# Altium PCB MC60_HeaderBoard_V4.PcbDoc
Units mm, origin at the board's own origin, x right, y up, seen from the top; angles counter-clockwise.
Board outline 51 x 30.45 mm, 2 copper layers (Top Layer, Bottom Layer); 33 components, 37 nets, 147 pads, 70 vias.
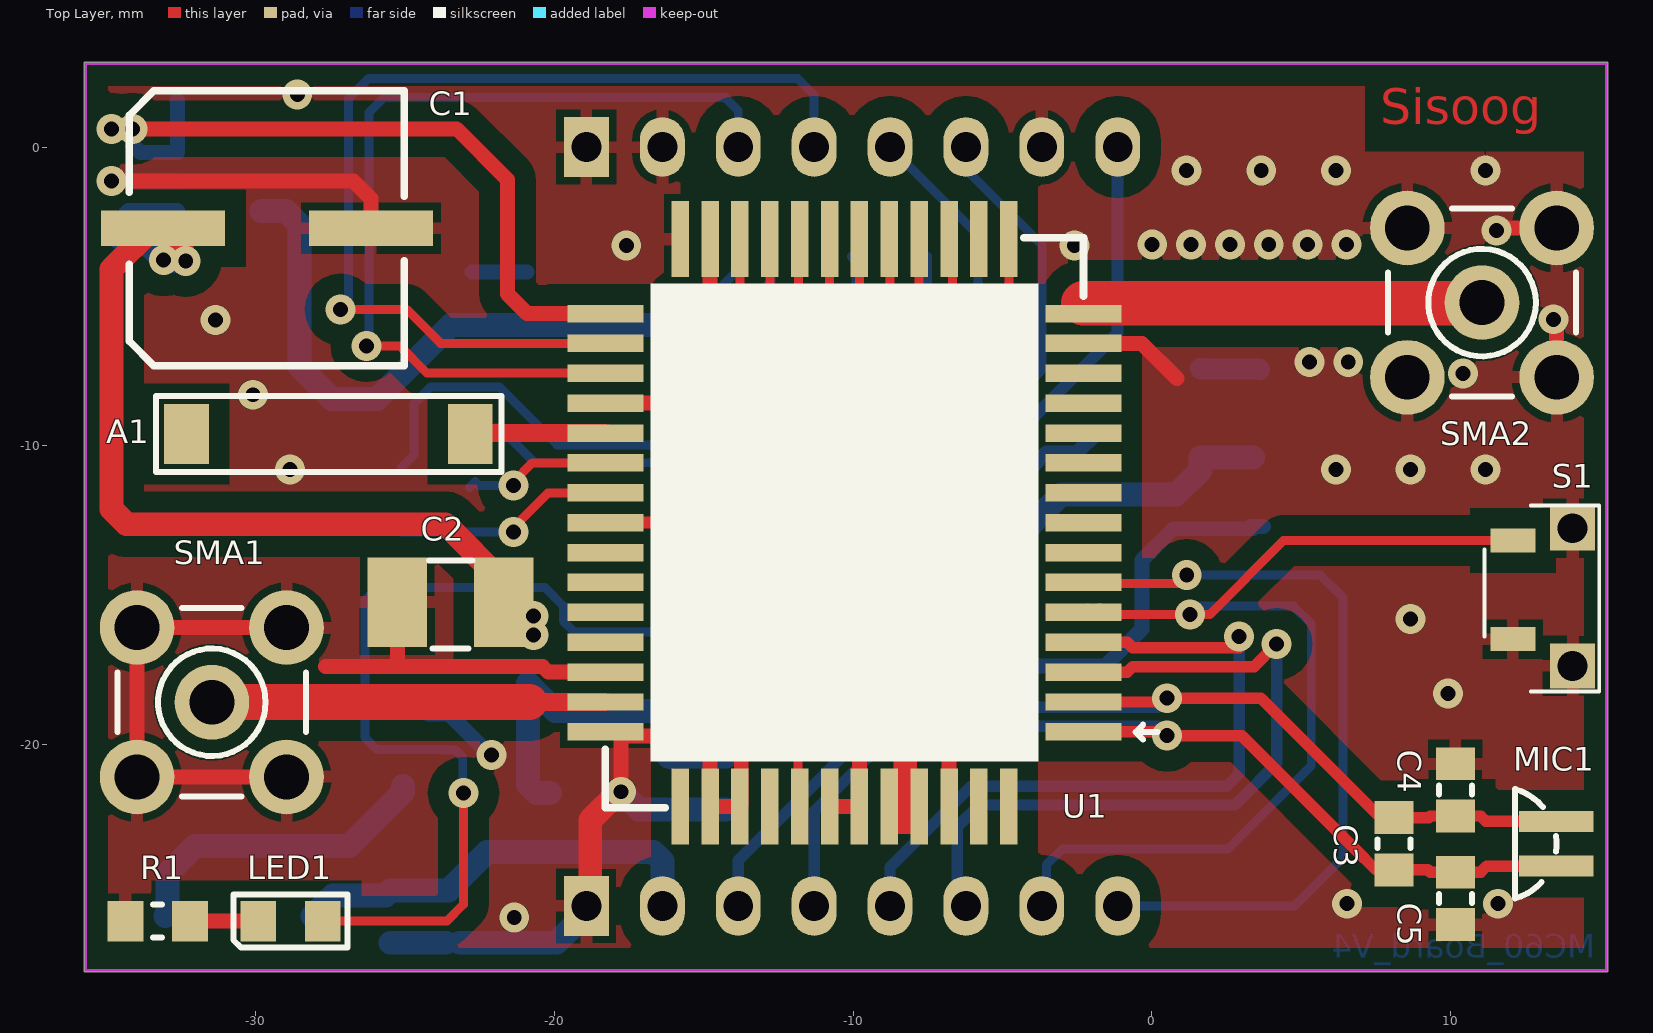
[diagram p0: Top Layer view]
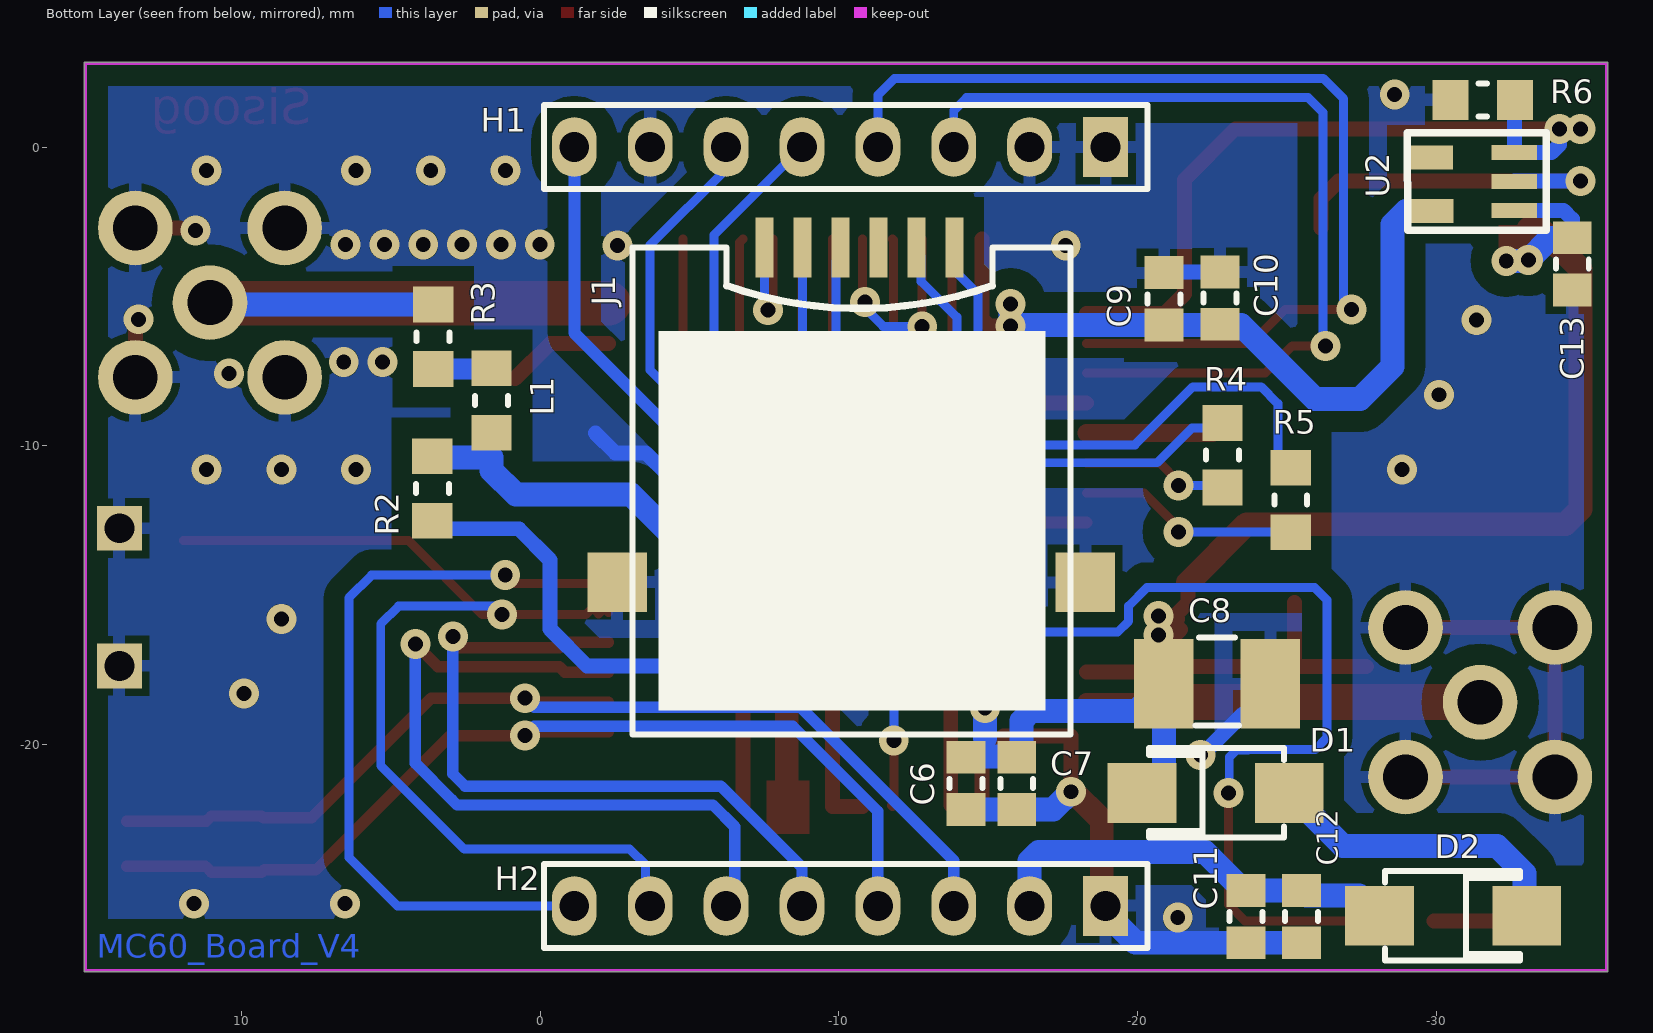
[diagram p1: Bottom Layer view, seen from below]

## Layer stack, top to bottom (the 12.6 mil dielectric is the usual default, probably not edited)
Top Solder: solder mask 0.0102, Solder Resist, Dk 3.5
Top Layer: signal copper 0.0356
Dielectric 1: dielectric 0.32, FR-4, Dk 4.8
Bottom Layer: signal copper 0.0356
Bottom Solder: solder mask 0.0102, Solder Resist, Dk 3.5

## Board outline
-35.687,-27.609 cw(c-35.687,-27.559) -35.737,-27.559 -35.737,2.794 cw(c-35.687,2.794) -35.687,2.844 15.214,2.844 cw(c15.214,2.794) 15.264,2.794 15.264,-27.559 cw(c15.214,-27.559) 15.214,-27.609

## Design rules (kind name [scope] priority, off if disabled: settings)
Clearance [All] p1: gap=0.3 except(0.7: Arc-Poly Track-Poly SMDPad-Poly THPad-Poly Via-Poly Fill-Poly Poly-Poly)
DiffPairsRouting [All] p1: maxlimit=0.254 minlimit=0.254 mostfreqgap=0.254 toplayer_minwidth=0.381 toplayer_maxwidth=0.381 toplayer_prefwidth=0.381 bottomlayer_minwidth=0.381 bottomlayer_maxwidth=0.381 bottomlayer_prefwidth=0.381 maxuncoupledlength=12.7
PolygonConnect [ISPAd] p1: connectstyle=Relief reliefconductorwidth=0.4 reliefentries=4 polygonreliefangle="90 Angle" airgapwidth=0.254
RoutingVias [All] p1: holewidth=0.5 width=1 viastyle="Through Hole" minholewidth=0.5 minwidth=0.5 maxholewidth=0.711 maxwidth=1.27
SolderMaskExpansion [All] p1: expansion=0.102
Width [All] p1: maxlimit=10 minlimit=0.254 preferedwidth=0.3
29 further rules are at their usual default settings.

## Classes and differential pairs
component class Main: A1 C13 H1 H2 J1 L1 R2 R3 R4 R5 SMA1 SMA2 U1
component class IO: C1 C2 C3 C4 C5 C6 C7 C8 C9 C10 C11 C12 D1 D2 LED1 MIC1 R1 R6 S1 U1
differential pair SPK: +SPK_P -SPK_N
differential pair MIC: +MIC_P -MIC_N

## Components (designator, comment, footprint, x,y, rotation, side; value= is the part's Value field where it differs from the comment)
A1 "AT9520 ANTENA 2.4GHz" "AT9520 ANTENA 2.4GHz" -27.559,-9.601 r0 top
C1 "1000uF 6V" "ALUMINUM \"CAP\"" -29.616,-2.718 r270 top (schematic designator C4)
C2 "220uF" "Tantalum Case B" -23.47,-15.24 r180 top (schematic designator C11)
C3 "10nF" "SMD 0805" 8.103,-23.317 r270 top (schematic designator C2)
C4 "10nF" "SMD 0805" 10.16,-21.514 r270 top (schematic designator C3)
C5 "10nF" "SMD 0805" 10.16,-25.146 r270 top (schematic designator C1)
C6 "100nF" "SMD 0805" -14.249,-21.297 r90 bottom (schematic designator C8)
C7 "10uF" "SMD 0805" -15.951,-21.297 r90 bottom
C8 "220uF Tantal" "Tantalum Case B" -22.657,-17.958 r180 bottom (schematic designator C13)
C9 "100nF" "SMD 0805" -20.879,-5.08 r270 bottom (schematic designator C10)
C10 "10uF" "SMD 0805" -22.758,-5.055 r270 bottom (schematic designator C9)
C11 "100nF" "SMD 0805" -23.622,-25.756 r90 bottom (schematic designator C5)
C12 "10uF" "SMD 0805" -25.476,-25.756 r90 bottom (schematic designator C6)
C13 "10uF" "SMD 0805" -34.544,-3.912 r90 bottom (schematic designator C12)
D1 "SS34" "DIODE DO-214AC SMD" -22.606,-21.615 r270 bottom (schematic designator D2)
D2 "M7" "DIODE DO-214AC SMD" -30.556,-25.73 r90 bottom (schematic designator D1)
H1 "HEDER 8PIN" "HEADER 8X1" -10.033,0 r0 bottom locked (schematic designator H2)
H2 "HEDER 8PIN" "HEADER 8X1" -10.033,-25.4 r0 bottom locked (schematic designator H1)
J1 "SIM CARD 6PIN SMT" "SIM CART 6PIN SMT TYPE" -10.414,-8.966 r0 bottom
L1 "feride bide 120R" 0805_1/8W 1.626,-8.484 r270 bottom
LED1 "LED SMD" "LED 0805" -28.829,-25.908 r180 top
MIC1 "Microphone" "Microphone SMD" 13.538,-23.317 r180 top
R1 "1K" 0805_1/8W -33.274,-25.908 r0 top (schematic designator R5)
R2 "10K" 0805_1/8W 3.607,-11.43 r90 bottom (schematic designator R6)
R3 "10R" 0805_1/8W 3.581,-6.35 r90 bottom (schematic designator R4)
R4 "10R" 0805_1/8W -22.835,-10.312 r90 bottom (schematic designator R3)
R5 "10R" 0805_1/8W -25.121,-11.811 r90 bottom (schematic designator R2)
R6 "100K" 0805_1/8W -31.547,1.575 r180 bottom (schematic designator R1)
S1 "Switch PB" "Switch - Push to On SMD stand 4.62mm" 13.081,-15.062 r180 top
SMA1 "SMA Antena" SMA -31.46,-18.582 r180 top locked
SMA2 "SMA GNSS" SMA 11.049,-5.207 r0 top
U1 "MC60" MC60 -10.287,-12.573 r180 top (schematic designator U2)
U2 "L2980" TSOT23 -32.604,-0.186 r270 bottom (schematic designator U1)

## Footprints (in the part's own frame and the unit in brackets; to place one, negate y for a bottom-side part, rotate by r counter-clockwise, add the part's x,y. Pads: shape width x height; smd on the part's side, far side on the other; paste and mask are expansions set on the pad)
0805_1/8W [mm] "Chip Resistor, 2-Leads, Body 2.0x1.3mm, IPC High Density _ (0.100 W)"
  rect 1.2x1.35 smd: 1(-1.079,0) 2(1.079,0)
  silkscreen extent -0.15,-0.55 0.15,0.55, body extent -1.02,-0.63 1.02,0.64, height 0.6
"ALUMINUM \"CAP\"" [mm]
  rect 1.2x4.16 smd: 1(0,-3.48) 2(0,3.48)
  silkscreen extent -4.6,-4.6 4.6,4.6
"AT9520 ANTENA 2.4GHz" [mm]
  rect 1.5x2 smd: 1(-4.75,0) 2(4.75,0)
  silkscreen extent -5.77,-1.27 5.79,1.27, body extent -4.88,-1.05 4.62,1.05, height 1.05
"DIODE DO-214AC SMD" [mm]
  rect 2x2.3 smd: 1(0,2.462) 2(0,-2.462)
  silkscreen extent -1.5,-2.34 1.5,2.29, body extent -1.32,-2.69 1.47,2.79, height 2.24
"HEADER 8X1" [mm]
  rect 1.5x2 hole 1: 1(-8.89,0)
  oval 1.5x2 hole 1: 2(-6.35,0) 3(-3.81,0) 4(-1.27,0) 5(1.27,0) 6(3.81,0) 7(6.35,0) 8(8.89,0)
  silkscreen extent -10.29,-1.4 9.91,1.4, body extent -10.08,-1.22 10.24,1.32, height 8.38
"LED 0805" [mm]
  rect 1.2x1.35 smd: 1(-1.079,0) 2(1.079,0)
  silkscreen extent -1.91,-0.89 1.91,0.89, body extent -1.65,-0.69 1.65,0.76, height 1.36
MC60 [mm]
  rect 2.54x0.584 smd: 1(-8,7) 2(-8,6) 3(-8,5) 4(-8,4) 5(-8,3) 6(-8,2) 7(-8,1) 8(-8,0) 9(-8,-1) 10(-8,-2) 11(-8,-3) 12(-8,-4) 13(-8,-5) 14(-8,-6) 15(-8,-7) 28(8,-7) 29(8,-6) 30(8,-5) 31(8,-4) 32(8,-3) 33(8,-2) 34(8,-1) 35(8,0) 36(8,1) 37(8,2) 38(8,3) 39(8,4) 40(8,5) 41(8,6) 42(8,7)
  rect 0.584x2.54 smd: 16(-5.5,-9.5) 17(-4.5,-9.492) 18(-3.5,-9.492) 19(-2.5,-9.492) 20(-1.5,-9.492) 21(-0.5,-9.492) 22(0.5,-9.492) 23(1.5,-9.492) 24(2.5,-9.492) 25(3.5,-9.492) 26(4.5,-9.492) 27(5.5,-9.492) 43(5.5,9.5) 44(4.5,9.492) 45(3.5,9.492) 46(2.5,9.492) 47(1.5,9.492) 48(0.5,9.492) 49(-0.5,9.492) 50(-1.5,9.492) 51(-2.5,9.492) 52(-3.5,9.492) 53(-4.5,9.492) 54(-5.5,9.5)
  silkscreen extent -10.48,-9.54 8,9.54
"Microphone SMD" [mm]
  rect 2.5x0.7 smd: 1(0,0.75) 2(0,-0.75)
  silkscreen extent 0,-1.83 1.38,1.83
"SIM CART 6PIN SMT TYPE" [mm]
  rect 2x2 smd: 0(-7.83,5.6) 0(7.83,5.6)
  rect 0.6x2 smd: 1(-3.45,-5.6) 2(-2.18,-5.6) 3(-0.91,-5.6) 4(0.36,-5.6) 5(1.63,-5.6) 6(2.9,-5.6)
  silkscreen extent -7.33,-5.6 7.33,10.7, body extent -7.7,-5.86 7.7,10.44, height 2.07
SMA [mm]
  round 2.5 hole 1.5: 1(0,0) 2(-2.5,2.5) 2(-2.5,-2.5) 2(2.5,2.5) 2(2.5,-2.5)
  silkscreen extent -3.15,-3.15 3.15,3.15, body extent -3.27,-4.56 27.08,4.44, height 49.75
"SMD 0805" [mm]
  rect 1.1x1.3 smd: 1(-0.876,0) 2(0.876,0)
  silkscreen extent -0.15,-0.55 0.15,0.55, body extent -1.02,-0.63 1.02,0.63, height 0.65
"Switch - Push to On SMD stand 4.62mm" [mm]
  rect 1.5x1.5 hole 1: 0(-1,2.305) 0(-1,-2.305)
  rect 1.5x0.8 smd: 1(1,-1.895) 2(1,1.405)
  silkscreen extent -1.89,-3.07 1.95,3.16, body extent -4.31,-3.01 2.31,2.9, height 6.6
"Tantalum Case B" [mm]
  rect 2x3 smd: 1(-1.782,0) 2(1.782,0)
  silkscreen extent -0.73,-1.41 0.73,1.54
TSOT23 [mm]
  rect 0.5x1.524 smd: 1(1.94,0) 2(0.97,0) 3(0,0)
  rect 0.8x1.524 smd: 4(0.17,-2.81) 5(1.95,-2.8)
  silkscreen extent -0.67,-3.58 2.6,1.07, body extent -0.53,-2.64 2.47,-0.14, height 1.1

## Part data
C1 C2 C8: library part CAP
C3 C4 C5 C6 C7 C9 C10 C11 C12 C13: library part "CAP NON"
D1 D2: library part Diode
L1: library part Inductor, "Inductor"
LED1: library part "LED 2PIN"
R1 R2 R3 R4 R5 R6: library part RESISTOR
SMA2: library part "SMA Antena"

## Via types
v1: diameter 1, hole 0.5, Top Layer to Bottom Layer, 40 vias
v2: diameter 1, hole 0.5, Top Layer to Bottom Layer, tented both sides, 30 vias

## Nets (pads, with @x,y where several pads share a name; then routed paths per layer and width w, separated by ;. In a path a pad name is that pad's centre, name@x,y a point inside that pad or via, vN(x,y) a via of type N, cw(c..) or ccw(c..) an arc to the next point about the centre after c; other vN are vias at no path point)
3V3: C9.2 C10.2 U1.26 U2.5 | length 25
  Top Layer w0.5: v1(-15.748,-5.994) -15.037,-5.994 -14.787,-5.745 U1.26
  Bottom Layer w0.8: U2.5 -28.979,-2.136 -28.522,-2.593 -28.522,-7.343 -27.432,-8.433 -25.938,-8.433 -23.461,-5.956 C9.2 -15.787,-5.956 v1(-15.748,-5.994) v1(-15.748,-5.258)
4V3: C1.1 C2.1 C6.2 C7.2 C8.1 C13.2 D1.2 L1.2 R2.2 U1.50 U1.51 U2.1 | length 75.8
  Top Layer w0.5: C2.1@-21.687,-14.584 C2.1 C2.1@-21.234,-15.693 ; C2.1@-21.234,-16.358 -21.438,-16.154 C2.1@-21.105,-15.822 ; v1(-20.701,-16.332) -20.697,-16.332 -20.621,-16.408 -20.57,-16.358 -20.978,-15.949 C2.1@-21.105,-15.822 ; v1(-20.701,-15.697) -20.98,-15.697 C2.1@-21.082,-15.799 ; C2.1@-21.234,-15.693 C2.1@-21.129,-15.799 ; C2.1@-21.234,-15.693 -21.34,-15.799 C2.1@-21.129,-15.799 ; C2.1@-21.129,-15.799 C2.1@-21.082,-15.799 ; C2.1@-21.129,-15.799 C2.1@-21.105,-15.822 ; C2.1@-21.105,-15.822 C2.1@-21.082,-15.799
  Top Layer w0.8: C1.1 -33.452,-2.718 -34.823,-4.089 -34.823,-12.116 -34.315,-12.624 -23.647,-12.624 C2.1@-21.687,-14.584 ; v1@-14.859,-18.034 -14.859,-17.272 -14.224,-16.637 v1(-8.763,-16.637) -8.255,-17.145 v1(-8.255,-17.374) -8.255,-21.597 U1.51@-8.001,-21.851
  Bottom Layer w0.5: C13.2 -34.544,-2.413 -34.257,-2.126 U2.1
  Bottom Layer w0.8: C13.2 -33.82,-3.036 v1(-33.071,-3.785) -33.045,-3.81 v1(-32.334,-3.81) ; v1(-20.701,-16.332) -20.701,-16.387 -20.679,-16.408 v1@-20.677,-16.407 ; D1.2 -20.599,-21.615 -20.875,-21.34 C8.1 -19.96,-18.872 -16.434,-18.872 -16.104,-19.202 C7.2@-16.104,-20.396 ; C7.2@-16.18,-20.396 C7.2@-16.104,-20.396 ; C7.2@-16.104,-20.422 C7.2@-16.104,-20.396 ; -14.884,-19.774 v1(-14.884,-18.771) ; C6.2@-14.275,-20.371 -14.249,-20.396 C7.2@-16.104,-20.396 ; v1(-8.255,-17.374) -8.255,-17.043 -8.153,-16.942 -8.458,-16.637 -8.153,-16.637 -8.103,-16.688 -3.048,-11.633 0.813,-11.633 1.626,-10.82 1.626,-10.389 R2.2@3.39,-10.389
  other v1: -14.884,-18.034
5V: C11.2 C12.2 D2.1 H2.2 | length 14.2
  Bottom Layer w0.8: D2.1 -27.408,-25.044 -25.641,-25.044 C12.2 C11.2 -23.534,-24.88 -22.25,-23.597 -16.688,-23.597 -16.383,-23.901 H2.2
ADC: H2.8 U1.6 | length 26.1
  Top Layer w0.3: U1.6 -2.192,-14.478 -2.065,-14.605 0.889,-14.605 v1(1.168,-14.326)
  Bottom Layer w0.3: H2.8 4.775,-25.4 6.401,-23.774 6.401,-15.088 5.639,-14.326 v1(1.168,-14.326)
DBG_RXD: H1.3 U1.30 | length 30.2
  Top Layer w0.3: v1(-26.289,-6.655) -25.171,-6.655 -24.259,-7.567 U1.30@-18.287,-7.567
  Bottom Layer w0.3: v1(-26.289,-6.655) -26.203,-6.568 -26.203,1.153 -25.705,1.651 -14.275,1.651 -13.843,1.219 H1.3
DBG_TXD: H1.4 U1.29 | length 34.1
  Top Layer w0.3: v1(-27.153,-5.436) -24.943,-5.436 -23.805,-6.573 U1.29
  Bottom Layer w0.3: v1@-26.889,-5.324 -26.889,1.61 -26.205,2.294 -11.862,2.294 -11.303,1.735 H1.4
GND: C1.2 C2.2 C4.1 C5.2 C6.1 C7.1 C8.2 C9.1 C10.1 C11.1 C12.1 C13.1 H1.1 H1.2 H1.7 H2.1 J1.0 R1.1 R6.1 S1.0 S1.2 SMA1.2 SMA2.2 U1.14 U1.27 U1.31 U1.40 U1.42 U1.44 U1.45 U1.48 U1.49 U2.2 | length 102.9
  Top Layer w0.4: v1(-16.192,-8.573) -15.85,-8.915 -15.85,-9.347 -13.703,-11.493
  Top Layer w0.5: v1(-34.823,-1.143) -26.721,-1.143 -26.137,-1.727 C1.2 ; SMA1.2@-28.96,-21.082 -33.96,-21.082 -33.96,-16.082 SMA1.2@-28.96,-16.082 ; -27.653,-17.389 -25.248,-17.389 ; C2.2 -25.248,-15.244 -25.248,-17.389 ; U1.40 -20.202,-17.573 -20.386,-17.389 -25.248,-17.389 ; U1.31 v1(-16.192,-8.573) ; v2(-17.768,-21.577) -17.768,-19.71 -15.506,-19.71 -14.787,-20.429 U1.44 U1.45 -13.741,-22.019 -13.741,-18.745 -13.183,-18.186 -10.262,-18.186 -9.787,-18.661 U1.49 U1.48 ; U1.14 -0.336,-6.573 0.838,-7.747 ; v2(11.533,-2.789) 11.615,-2.707 SMA2.2@13.549,-2.707 ; v2(13.447,-5.765) 13.549,-5.867 SMA2.2@13.549,-7.707
  Top Layer w0.8: H2.1@-18.796,-25.4 -18.796,-22.53 v2@-17.805,-21.539
  Bottom Layer w0.5: v1(-34.823,-1.143) -32.617,-1.143 U2.2 ; C8.2@-24.206,-18.974 -23.521,-18.974 -22.317,-20.177 -22.184,-20.177 -22.098,-20.091 v1(-22.098,-20.345) ; C10.1 C9.1@-20.904,-4.179 ; v2(-11.887,-13.564) v2@-11.887,-13.386 ; -10.541,-13.513 -6.807,-13.513 -3.531,-10.236 -2.515,-10.236 -1.854,-9.576 ; v1@6.325,-25.375 6.477,-25.375 v1(6.528,-25.324) v1@6.604,-25.324 ; v1@11.582,-25.527 v1(11.582,-25.324)
  Bottom Layer w0.8: C12.1 C11.1 ; C11.1@-23.165,-26.631 -19.926,-26.631 H2.1@-18.72,-25.425 ; v2(-17.768,-21.577) -17.171,-22.173 C7.1 C6.1
  other v1: -5.486,-16.104 -28.6,1.753
  other v2: -21.339,-25.791 9.911,-18.291 8.661,-15.791 -10.033,-13.564 -8.28,-13.564 -28.839,-10.791 6.161,-10.791 8.661,-10.791 11.161,-10.791 -30.089,-8.291 10.413,-7.584 5.272,-7.198 6.572,-7.198 -31.339,-5.791 -17.589,-3.291 -2.588,-3.293 0.011,-3.264 1.311,-3.264 2.611,-3.264 3.911,-3.264 5.211,-3.264 6.511,-3.264 1.161,-0.791 3.661,-0.791 6.161,-0.791 11.161,-0.791
GSMRX: H1.5 R5.2 | length 32.5
  Bottom Layer w0.3: R5.2 -24.689,-10.3 -24.689,-8.585 -24.13,-8.026 -21.844,-8.026 -19.903,-9.967 -7.427,-9.967 -5.817,-8.357 -5.817,-2.946 H1.5
GSMTX: H1.6 R4.2 | length 29.5
  Bottom Layer w0.3: R4.2 -22.663,-9.405 -21.815,-9.405 -20.652,-10.567 -6.782,-10.567 -3.683,-7.468 -3.683,-3.277 -6.223,-0.737 H1.6
MIC_N: C3.1 C4.2 H2.3 MIC1.2 U1.2 | length 36.1
  Top Layer w0.381: U1.2 0.381,-18.573 v1(0.508,-18.446) 3.65,-18.446 7.645,-22.441 C3.1 9.268,-22.441 9.32,-22.39 C4.2 11,-22.39 11.178,-22.567 MIC1.2 MIC1.2@13.843,-22.567
  Bottom Layer w0.381: H2.3 -13.843,-23.877 -8.721,-18.755 0.198,-18.755 v1(0.508,-18.446)
MIC_P: C3.2 C5.1 H2.4 MIC1.1 U1.1 | length 34.4
  Top Layer w0.381: U1.1 0.381,-19.573 v1(0.508,-19.7) 3.01,-19.7 6.792,-23.482 7.503,-24.193 C3.2 9.242,-24.193 9.32,-24.27 C5.1 11,-24.27 11.203,-24.067 MIC1.1 MIC1.1@13.843,-24.067
  Bottom Layer w0.381: H2.4 -11.303,-22.235 -8.458,-19.39 0.198,-19.39 v1(0.508,-19.7)
NetA1_2: A1.2 U1.32 | length 5
  Top Layer w0.5: A1.2@-23.063,-9.017 A1.2@-22.507,-9.573
  Top Layer w0.6: A1.2@-22.507,-9.573 U1.32
NetD1_2: D1.1 D2.2 | length 10.7
  Bottom Layer w0.8: D2.2 -32.942,-25.654 -32.942,-24.31 -32.025,-23.393 -26.873,-23.393 -25.068,-21.588 D1.1@-25.068,-21.387
NetJ1_1: J1.1 U1.16 | length 23.1
  Top Layer w0.3: v1(-14.554,-8.484) -14.554,-9.576 -13.563,-10.567 -6.249,-10.567 -4.787,-9.105 U1.16
  Bottom Layer w0.3: v1@-14.656,-8.484 -14.656,-4.928 -13.843,-4.115 J1.1@-13.843,-3.671
NetJ1_2: J1.2 U1.18 | length 20.3
  Top Layer w0.3: v1@-12.488,-8.574 v1(-12.746,-8.378) -12.746,-9.783 -12.563,-9.967 -7.3,-9.967 -6.67,-9.337 -6.67,-3.198 U1.18
  Bottom Layer w0.3: v1(-12.746,-8.378) -12.882,-8.378 -13.945,-7.315 -13.945,-5.694 -12.746,-4.496 J1.2@-12.746,-3.646
NetJ1_4: J1.4 U1.20 | length 9.2
  Top Layer w0.3: v1(-9.906,-7.62) -8.992,-7.62 -8.763,-7.391 U1.20@-8.763,-3.457
  Bottom Layer w0.3: J1.4@-10.054,-3.671 -9.906,-3.819 v1(-9.906,-7.62)
NetJ1_5: J1.5 U1.21 | length 14.1
  Top Layer w0.3: v1(-9.906,-9.017) -10.668,-9.017 -10.998,-8.687 -10.998,-6.629 -10.744,-6.375 -9.959,-6.375 -9.787,-6.203 U1.21
  Bottom Layer w0.3: v1(-9.906,-9.017) -9.144,-9.017 -8.784,-8.657 J1.5@-8.784,-3.671
NetJ1_6: J1.6 U1.19 | length 4.2
  Top Layer w0.3: v1@-7.787,-5.461 U1.19
  Bottom Layer w0.3: v1@-7.514,-5.461 J1.6@-7.514,-3.671
  other v1: -7.62,-5.461
NetL1_1: L1.1 R3.1 | length 2
  Bottom Layer w0.7: L1.1 1.65,-7.429 R3.1 R3.1@3.607,-7.454
NetLED1_2: LED1.2 R1.2 | length 2.3
  Top Layer w0.5: R1.2 LED1.2
NETLIGHT: LED1.1 U1.47 | length 39.2
  Top Layer w0.3: LED1.1 -23.597,-25.908 -23.038,-25.349 v1(-23.038,-21.615) v1@-23.063,-21.615 ; v1(-11.836,-19.863) -11.836,-21.962 -11.76,-22.038 U1.47
  Top Layer w0.5: LED1.1 LED1.1@-27.737,-25.895
  Bottom Layer w0.3: v1@-23.063,-21.615 -23.063,-20.422 -23.298,-20.187 -23.695,-20.187 -23.717,-20.165 -25.936,-20.165 -26.34,-19.761 -26.34,-15.164 -25.923,-14.747 -20.307,-14.747 -19.694,-15.361 -19.694,-15.866 -19.329,-16.231 -12.319,-16.231 -11.836,-16.713 v1(-11.836,-19.863)
NetR2_1: R5.1 U1.34 | length 7.7
  Top Layer w0.3: v1@-21.514,-12.878 -20.209,-11.573 U1.34
  Top Layer w0.4: v1@-21.514,-12.878 v1(-21.361,-12.878)
  Bottom Layer w0.3: R5.1 -25.108,-12.878 v1(-21.361,-12.878)
NetR3_1: R4.1 U1.33 | length 5.1
  Top Layer w0.3: v1(-21.361,-11.328) -21.361,-11.201 -20.733,-10.573 U1.33
  Bottom Layer w0.3: R4.1 -22.645,-11.201 -22.518,-11.328 v1(-21.361,-11.328)
NetR4_2: R3.2 SMA2.1 U1.15 | length 20
  Top Layer w1.5: -2.286,-5.231 SMA2.1@10.438,-5.231
  Bottom Layer w0.8: R3.2 10.731,-5.271 SMA2.1@10.795,-5.207
NetR6_1: R2.1 U1.52 | length 18.6
  Top Layer w0.5: U1.52 -6.787,-17.43 v1(-6.731,-17.374)
  Bottom Layer w0.5: v1(-6.731,-17.374) -1.575,-17.374 -0.33,-16.129 -0.33,-13.818 0.711,-12.776 3.378,-12.776 3.302,-12.7 R2.1@3.734,-12.7
NetSMA1_1: SMA1.1 U1.41 | length 12.3
  Top Layer w0.6: SMA1.1@-30.567,-18.582 SMA1.1@-30.558,-18.573 ; -20.828,-18.573 U1.41
  Top Layer w1.2: SMA1.1@-30.558,-18.573 -20.828,-18.573
NetU2_22: U1.22 U1.24 | length 7.5
  Top Layer w0.3: v1(-12.787,-6.005) U1.24 ; v1@-10.787,-5.182 U1.22
  Bottom Layer w0.3: v1(-12.787,-6.005) -11.481,-6.005 -10.795,-5.319 -10.871,-5.243 v1(-10.871,-5.182)
NetU2_23: U1.23 U1.25 | length 10.2
  Top Layer w0.3: U1.25 -13.787,-7.016 -13.437,-7.366 -12.141,-7.366 -11.821,-7.046 -11.821,-3.115 U1.23
PWRKEY: H2.7 S1.1 U1.5 | length 36.6
  Top Layer w0.3: U1.5 -2.147,-15.433 -1.959,-15.621 -1.756,-15.418 -1.527,-15.646 v1(1.27,-15.646) 1.93,-15.646 4.41,-13.167 S1.1@11.929,-13.167
  Bottom Layer w0.3: H2.7@-3.531,-25.705 -3.531,-24.028 -2.997,-23.495 2.54,-23.495 5.334,-20.701 5.334,-15.962 4.739,-15.367 1.549,-15.367 v1(1.27,-15.646)
RI: H1.8 U1.35 | length 26.1
  Top Layer w0.4: U1.35 -15.24,-12.573 -14.859,-12.192 v1(-14.91,-12.192)
  Bottom Layer w0.4: v1(-14.91,-12.192) -7.112,-12.192 -1.143,-6.223 H1.8
SPI_CLK: 
SPI_CS: 
SPI_MISO: 
SPI_MOSI: 
SPK_N: H2.5 U1.4 | length 24.5
  Top Layer w0.381: U1.4 -0.826,-16.573 -0.644,-16.755 2.921,-16.755 v1(2.921,-16.383)
  Bottom Layer w0.381: H2.5 -8.763,-24.105 -6.045,-21.387 2.515,-21.387 2.921,-20.98 v1(2.921,-16.383)
SPK_P: H2.6 U1.3 | length 25.2
  Top Layer w0.381: U1.3 -0.826,-17.573 -0.644,-17.39 3.422,-17.39 v1(4.175,-16.637)
  Bottom Layer w0.381: H2.6 -6.511,-25.112 -6.511,-22.75 -5.782,-22.022 2.778,-22.022 2.964,-21.836 4.175,-20.624 v1(4.175,-16.637)
VGNSS_EN: R6.2 U1.28 U2.3 | length 25.4
  Top Layer w0.5: v1(-34.112,0.61) -23.266,0.61 -21.565,-1.092 -21.565,-4.919 -20.911,-5.573 U1.28
  Bottom Layer w0.5: v1@-34.823,0.457 v1(-34.823,0.61) v1(-34.112,0.61) -34.112,0.076 -33.85,-0.186 U2.3 -32.604,1.553 R6.2
pads on no net: A1.1 J1.3 U1.7 U1.8 U1.9 U1.10 U1.11 U1.12 U1.13 U1.17 U1.36 U1.37 U1.38 U1.39 U1.43 U1.46 U1.53 U1.54 U2.4

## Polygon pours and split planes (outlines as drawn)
GND on Bottom Layer "Bottom Layer-No Net" (solid, remove dead copper, pour order 10): 15.265,2.819 -35.687,2.819 -35.687,-27.584 -35.738,-27.635 -35.712,-27.61 15.291,-27.61
GND on Top Layer "Bottom Layer-No Net" (solid, remove dead copper, pour order 12): 15.291,2.794 -35.662,2.794 -35.712,2.845 -35.712,-27.559 15.24,-27.559 15.265,-27.584

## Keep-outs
Keep-Out Layer:
  lines w0.1: -26.035,2.794 15.214,2.794 15.214,-27.559 -35.687,-27.559 -35.687,2.794 -23.876,2.794

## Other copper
Top Layer:
  rectangle net 3V3: -16.027,-6.147 -15.494,-5.004
  rectangle net 4V3: -9.017,-22.987 -7.569,-21.209
  rectangle net 4V3: -33.249,-4.115 -32.08,-2.616
  text "Sisoog" at 7.645,0.762 h1.2
Bottom Layer:
  text "MC60_Board_V4" at 14.834,-27.127 h0.8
